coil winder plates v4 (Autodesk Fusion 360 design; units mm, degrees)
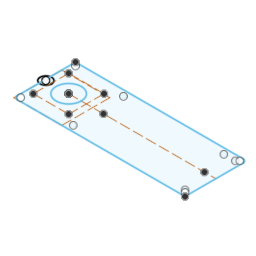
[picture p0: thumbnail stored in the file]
sketch "plates" plane through (0, 0, 0) normal (0, 1, 0) x axis (1, 0, 0)
  line L1 (41, -27) -> (41, 15)
  line L2 (-1, 15) -> (-1, -27)
  line L3 (41, 15) -> (-1, 15)
  line L4 (-1, -27) -> (41, -27)
  line L5 (4.5, -15.5) -> (4.5, 15.5)
  line L6 (4.5, 15.5) -> (35.5, 15.5)
  line L7 (35.5, -15.5) -> (4.5, -15.5)
  line L8 (35.5, 15.5) -> (35.5, -15.5)
  line L9 (146, -27) -> (2, -27)
  line L10 (149, 24) -> (149, -24)
  line L11 (2, 27) -> (146, 27)
  line L12 (-1, -24) -> (-1, 24)
  line L13 (149, 0) -> (20, 0)
  circle C1 centre (4.5, 15.5) radius 1.5
  circle C2 centre (20, 0) radius 11
  circle C3 centre (35.5, -15.5) radius 1.5
  circle C4 centre (35.5, 15.5) radius 1.5
  circle C5 centre (4.5, -15.5) radius 1.5
  circle C6 centre (139, 0) radius 1.5
  circle C7 centre (50.5, 0) radius 1.5
  circle C8 centre (144, -22) radius 1.5
  circle C9 centre (46, 22) radius 1.5
  circle C10 centre (144, 22) radius 1.5
  arc A1 centre (146, 24) radius 3 clockwise from (146, 27) to (149, 24)
  arc A2 centre (2, 24) radius 3 clockwise from (-1, 24) to (2, 27)
  arc A3 centre (146, -24) radius 3 clockwise from (149, -24) to (146, -27)
  arc A4 centre (2, -24) radius 3 clockwise from (2, -27) to (-1, -24)
  circle C11 centre (46, -22) radius 1.5
  circle C12 centre (134, 22) radius 1.5
  point P10 (20, 0)
  point P16 (20, 0)
  point P17 (20, 0)
  point P15 (35.5, -15.5)
  point P18 (35.5, -15.5)
  point P8 (35.5, 15.5)
  point P12 (35.5, 15.5)
  point P5 (4.5, 15.5)
  point P13 (4.5, 15.5)
  point P2 (4.5, -15.5)
  point P14 (4.5, -15.5)
  point P21 (20, 0)
  point P23 (139, 0)
  point P24 (50.5, 0)
  point P22 (149, 0)
  point P20 (-1, 27)
  point P19 (149, -27)
  point P7 (-1, -27)
  point P3 (-1, 15)
  point P4 (41, 15)
  point P11 (0, 0)
  point P25 (144, -22)
  point P26 (46, 22)
  point P27 (144, 22)
  point P40 (46, -22)
  point P41 (134, 22)
  perpendicular L5 L6
  parallel L6 L7
  parallel L5 L8
  horizontal L6
  coincident P10 P16
  perpendicular L2 L4
  parallel L3 L4
  parallel L1 L2
  horizontal L4
  coincident P16 P17
  coincident P15 P18
  coincident P8 P12
  coincident P5 P13
  coincident P2 P14
  horizontal L9
  vertical L10
  horizontal L11
  vertical L12
  coincident P17 P21
  coincident L13 P23
  coincident L13 P24
  coincident L10 P22
  tangent L10 A1
  tangent L11 A1
  coincident P20 L11
  coincident P20 L12
  tangent L11 A2
  tangent L12 A2
  equal A1 A2
  coincident P19 L10
  coincident P19 L9
  tangent L10 A3
  tangent L9 A3
  coincident P7 L9
  coincident P7 L12
  tangent L9 A4
  tangent L12 A4
  dimension "d1" diameter C2 = 22
  dimension "d2" distance P14 P15 = 31
  dimension "d3" distance P13 P14 = 31
  dimension "d4" distance P3 P4 = 42
  dimension "d5" distance P3 P7 = 42
  dimension "d6" diameter C3 = 3
  dimension "d7" diameter C4 = 3
  dimension "d8" diameter C1 = 3
  dimension "d9" diameter C5 = 3
  dimension "d10" distance P10 P11 = 20
  dimension "d17" distance P7 P19 = 150
  dimension "d18" distance P7 P20 = 54
  dimension "d19" diameter C6 = 3
  dimension "d20" diameter C7 = 3
  dimension "d21" distance P23 P24 = 88.5
  dimension "d22" distance L10 P23 = 10
  dimension "d23" diameter C8 = 3
  dimension "d24" distance L10 P25 = 5
  dimension "d25" distance L9 P25 = 5
  dimension "d26" diameter C9 = 3
  dimension "d27" distance L1 P26 = 5
  dimension "d28" distance L11 P26 = 5
  dimension "d29" diameter C10 = 3
  dimension "d30" distance L10 P27 = 5
  dimension "d31" distance L11 P27 = 5
  dimension "d32" radius A1 = 3
  dimension "d33" radius A3 = 3
  dimension "d34" radius A4 = 3
  dimension "d35" diameter C11 = 3
  dimension "d36" distance L9 P40 = 5
  dimension "d37" distance L1 P40 = 5
  dimension "d42" distance L11 L13 = 27
  dimension "d43" diameter C12 = 3
  dimension "d44" distance L11 P41 = 5
  dimension "d45" distance P27 P41 = 10
sketch "foot circle" plane through (0, 0, 0) normal (0, 1, 0) x axis (1, 0, 0)
  circle C1 centre (0, 0) radius 1.5
  circle C2 centre (0, 0) radius 5
  point P1 (0, 0)
  point P2 (0, 0)
  point P3 (0, 0)
  coincident P1 P2
  coincident P1 P3
  dimension "d46" diameter C1 = 3
  dimension "d47" diameter C2 = 10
